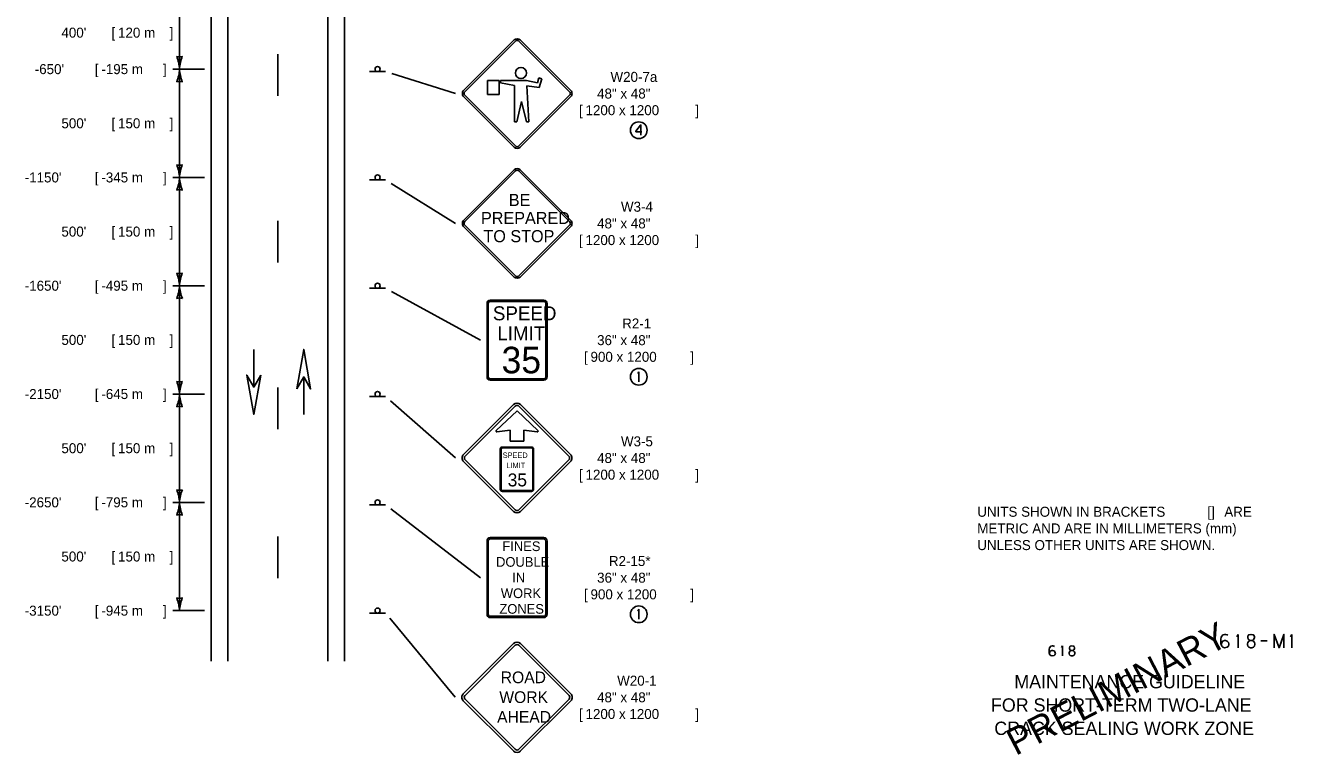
# Model space of a CAD drawing. Extents: x 49987.3 to 50021, y 49987.6 to 50011.4.
# Drawn here: x 49987.72 to 49995.31, y 50000.44 to 50004.82 of the extents above; entities that cross this region are included whole.
import ezdxf

# ---------------------------------------------------------------- set-up
doc = ezdxf.new("R2010")
doc.units = 0
for name, color, linetype in [('Level 1', 7, 'Continuous'), ('Level 2', 7, 'Continuous'), ('Level 3', 7, 'Continuous')]:
    doc.layers.add(name, color=color, linetype=linetype)

msp = doc.modelspace()

# ---------------------------------------------------------------- linework, layer by layer
at = {"layer": 'Level 1'}
for p, q in [((49988.8324, 50001.0011), (49988.8324, 50007.6183)), ((49988.9323, 50001.0011), (49988.9324, 50007.6183)), ((49989.5323, 50001.0011), (49989.5324, 50007.6183)), ((49989.6323, 50001.0011), (49989.6323, 50007.6183)), ((49990.6501, 50004.7296), (49990.346, 50004.4256)), ((49990.6571, 50004.7227), (49990.3531, 50004.4185)), ((49990.9822, 50004.4185), (49990.6784, 50004.7227)), ((49990.9894, 50004.4256), (49990.6854, 50004.7296)), ((49989.2324, 50004.3938), (49989.2324, 50004.6437)), ((49989.8783, 50004.5393), (49989.7824, 50004.5393)), ((49990.4894, 50004.402), (49990.4894, 50004.4869)), ((49990.4894, 50004.4869), (49990.5588, 50004.4869)), ((49990.5588, 50004.4869), (49990.5588, 50004.402)), ((49990.7232, 50004.4865), (49990.5667, 50004.4865)), ((49990.5667, 50004.4865), (49990.5667, 50004.4725)), ((49990.5667, 50004.4725), (49990.6516, 50004.4557)), ((49990.7887, 50004.4713), (49990.7232, 50004.4865)), ((49990.7984, 50004.5014), (49990.7887, 50004.4713)), ((49990.8149, 50004.4971), (49990.7984, 50004.5014)), ((49990.7998, 50004.4452), (49990.8149, 50004.4971)), ((49990.346, 50004.3904), (49990.6501, 50004.0864)), ((49990.3531, 50004.3974), (49990.6571, 50004.0934)), ((49990.5588, 50004.402), (49990.4894, 50004.402)), ((49990.6516, 50004.4557), (49990.6516, 50004.2391)), ((49990.6784, 50004.0934), (49990.9822, 50004.3974)), ((49990.6854, 50004.0864), (49990.9894, 50004.3904)), ((49990.7372, 50004.2391), (49990.7259, 50004.4536)), ((49990.7259, 50004.4536), (49990.7998, 50004.4452)), ((49990.6655, 50004.2391), (49990.6944, 50004.3612)), ((49990.6944, 50004.3612), (49990.7234, 50004.2391)), ((49990.6516, 50004.2391), (49990.6655, 50004.2391)), ((49990.7234, 50004.2391), (49990.7372, 50004.2391)), ((49990.6501, 50003.9502), (49990.346, 50003.6462)), ((49990.6571, 50003.9432), (49990.3531, 50003.6391)), ((49990.9822, 50003.6391), (49990.6784, 50003.9432)), ((49990.9894, 50003.6462), (49990.6854, 50003.9502)), ((49989.8783, 50003.8893), (49989.7824, 50003.8893)), ((49989.2324, 50003.3939), (49989.2324, 50003.6438)), ((49990.346, 50003.6109), (49990.6501, 50003.3069)), ((49990.3531, 50003.6179), (49990.6571, 50003.3139)), ((49990.6784, 50003.3139), (49990.9822, 50003.6179)), ((49990.6854, 50003.3069), (49990.9894, 50003.6109)), ((49989.8783, 50003.2393), (49989.7824, 50003.2393)), ((49990.4868, 50003.1479), (49990.4868, 50002.7079)), ((49990.4944, 50003.1479), (49990.4944, 50002.7079)), ((49990.828, 50003.1679), (49990.5055, 50003.1679)), ((49990.828, 50003.1599), (49990.5055, 50003.1599)), ((49990.8393, 50002.7079), (49990.8393, 50003.1479)), ((49990.8468, 50002.7079), (49990.8468, 50003.1479)), ((49989.0874, 50002.8722), (49989.0874, 50002.6463)), ((49989.0877, 50002.8722), (49989.0877, 50002.6463)), ((49989.2324, 50002.394), (49989.2324, 50002.6439)), ((49989.3871, 50002.4819), (49989.3871, 50002.708)), ((49989.3874, 50002.4819), (49989.3874, 50002.708)), ((49990.5055, 50002.696), (49990.828, 50002.696)), ((49990.5055, 50002.688), (49990.828, 50002.688)), ((49989.8783, 50002.5894), (49989.7824, 50002.5894)), ((49990.6454, 50002.5414), (49990.3461, 50002.2421)), ((49990.6555, 50002.5313), (49990.3562, 50002.232)), ((49990.6668, 50002.5029), (49990.5423, 50002.3856)), ((49990.6454, 50002.5414), (49990.6454, 50002.5414)), ((49990.6555, 50002.5313), (49990.6555, 50002.5313)), ((49990.7912, 50002.3856), (49990.6668, 50002.5029)), ((49990.9773, 50002.232), (49990.678, 50002.5313)), ((49990.9874, 50002.2421), (49990.6881, 50002.5414)), ((49990.5464, 50002.377), (49990.6264, 50002.387)), ((49990.6264, 50002.387), (49990.6264, 50002.3215)), ((49990.7071, 50002.3215), (49990.7071, 50002.387)), ((49990.7071, 50002.387), (49990.7871, 50002.377)), ((49990.5664, 50002.0326), (49990.5664, 50002.2739)), ((49990.5716, 50002.0326), (49990.5716, 50002.2739)), ((49990.5789, 50002.2864), (49990.7536, 50002.2864)), ((49990.5789, 50002.2812), (49990.7536, 50002.2812)), ((49990.6264, 50002.3215), (49990.7071, 50002.3215)), ((49990.6662, 50002.2864), (49990.6662, 50002.2864)), ((49990.7609, 50002.2739), (49990.7609, 50002.0326)), ((49990.7661, 50002.2739), (49990.7661, 50002.0326)), ((49990.3461, 50002.1993), (49990.6454, 50001.9)), ((49990.3562, 50002.2094), (49990.6555, 50001.9101)), ((49990.678, 50001.9101), (49990.9773, 50002.2094)), ((49990.6881, 50001.9), (49990.9874, 50002.1993)), ((49990.7536, 50002.0253), (49990.5789, 50002.0253)), ((49990.7536, 50002.0201), (49990.5789, 50002.0201)), ((49989.8783, 50001.9393), (49989.7824, 50001.9393)), ((49989.2324, 50001.4997), (49989.2324, 50001.7497)), ((49990.828, 50001.7426), (49990.5056, 50001.7426)), ((49990.828, 50001.7346), (49990.5056, 50001.7346)), ((49990.4868, 50001.7225), (49990.4868, 50001.2825)), ((49990.4944, 50001.7225), (49990.4944, 50001.2825)), ((49990.8393, 50001.2825), (49990.8393, 50001.7225)), ((49990.8468, 50001.2825), (49990.8468, 50001.7225)), ((49989.8783, 50001.2893), (49989.7824, 50001.2893)), ((49990.5056, 50001.2707), (49990.828, 50001.2707)), ((49990.5056, 50001.2626), (49990.828, 50001.2626)), ((49990.6455, 50001.1069), (49990.3446, 50000.8061)), ((49990.6555, 50001.0967), (49990.3548, 50000.796)), ((49990.6455, 50001.1069), (49990.6455, 50001.1069)), ((49990.6555, 50001.0967), (49990.6555, 50001.0967)), ((49990.9789, 50000.796), (49990.6782, 50001.0967)), ((49990.9891, 50000.8061), (49990.6884, 50001.1069)), ((49990.3446, 50000.7631), (49990.6455, 50000.4624)), ((49990.3548, 50000.7733), (49990.6555, 50000.4725)), ((49990.6669, 50000.7846), (49990.6669, 50000.7846)), ((49990.6669, 50000.7846), (49990.6669, 50000.7846)), ((49990.6669, 50000.7846), (49990.6669, 50000.7846)), ((49990.6782, 50000.4725), (49990.9789, 50000.7733)), ((49990.6884, 50000.4624), (49990.9891, 50000.7631))]:
    msp.add_line(p, q, dxfattribs=at)
for points in [[(49990.7982, 50004.5012), (49990.7984, 50004.5014)], [(49990.5585, 50004.402), (49990.5588, 50004.4024)], [(49990.7993, 50004.4453), (49990.8, 50004.4461)]]:
    msp.add_lwpolyline(points, dxfattribs=at)
for points in [[(49989.3454, 50002.6355), (49989.3871, 50002.8722), (49989.429, 50002.6355), (49989.3871, 50002.7077)], [(49989.1295, 50002.7186), (49989.0877, 50002.4821), (49989.0459, 50002.7186), (49989.0877, 50002.6463)]]:
    msp.add_lwpolyline(points, close=True, dxfattribs=at)
for centre, radius in [((49989.8303, 50004.5547), 0.0152), ((49990.6901, 50004.531), 0.0334), ((49989.8303, 50003.9045), 0.0152), ((49989.8303, 50003.2546), 0.0152), ((49989.8303, 50002.6046), 0.0152), ((49989.8303, 50001.9545), 0.0152), ((49989.8303, 50001.3046), 0.0152)]:
    msp.add_circle(centre, radius, dxfattribs=at)
for centre, radius, start, end in [((49990.6677, 50004.7121), 0.025, 45, 135), ((49990.6677, 50004.7121), 0.015, 45, 135), ((49990.3637, 50004.4081), 0.025, 135, 225), ((49990.3637, 50004.4081), 0.015, 135, 225), ((49990.9717, 50004.4081), 0.015, 315, 45.00024), ((49990.9717, 50004.4081), 0.025, 315, 45.00024), ((49990.6677, 50004.104), 0.025, 225, 314.99957), ((49990.6677, 50004.104), 0.015, 225, 314.99957), ((49990.6677, 50003.9326), 0.025, 45, 135), ((49990.6677, 50003.9326), 0.015, 45, 135), ((49990.3637, 50003.6286), 0.025, 135, 225), ((49990.3637, 50003.6286), 0.015, 135, 225), ((49990.9717, 50003.6286), 0.015, 315, 45.00024), ((49990.9717, 50003.6286), 0.025, 315, 45.00024), ((49990.6677, 50003.3246), 0.025, 225, 314.99957), ((49990.6677, 50003.3246), 0.015, 225, 314.99957), ((49990.6668, 50002.52), 0.0302, 45.00007, 134.99993), ((49990.6668, 50002.52), 0.016, 45.00007, 134.99993), ((49990.5459, 50002.382), 0.00508, 134.62874, 275.82948), ((49990.7876, 50002.382), 0.00509, 264.38259, 45.16491), ((49990.5789, 50002.2739), 0.0125, 90, 180), ((49990.5789, 50002.2739), 0.00728, 90, 180), ((49990.7536, 50002.2739), 0.0125, 360, 90), ((49990.7536, 50002.2739), 0.00728, 360, 90), ((49990.3674, 50002.2207), 0.0302, 134.99993, 225.00008), ((49990.3674, 50002.2207), 0.016, 134.99993, 225.00008), ((49990.9661, 50002.2207), 0.016, 314.99993, 45.00007), ((49990.9661, 50002.2207), 0.0302, 314.99993, 45.00008), ((49990.5789, 50002.0326), 0.0125, 180, 270), ((49990.5789, 50002.0326), 0.00728, 180, 270), ((49990.7536, 50002.0326), 0.00728, 270, 360), ((49990.7536, 50002.0326), 0.0125, 270, 360), ((49990.6668, 50001.9214), 0.0302, 225.00007, 314.99993), ((49990.6668, 50001.9214), 0.016, 225.00007, 314.99993), ((49990.6668, 50001.0852), 0.0304, 45.00008, 134.99993), ((49990.6668, 50001.0852), 0.016, 45.00008, 134.99993), ((49990.366, 50000.7845), 0.0304, 134.99993, 225.00008), ((49990.366, 50000.7845), 0.016, 134.99993, 225.00008), ((49990.9675, 50000.7845), 0.016, 314.99993, 45.00007), ((49990.9675, 50000.7845), 0.0304, 314.99993, 45.00008), ((49990.6668, 50000.4837), 0.0304, 225.00007, 314.99993), ((49990.6668, 50000.4837), 0.016, 225.00007, 314.99993)]:
    msp.add_arc(centre, radius, start, end, dxfattribs=at)
for centre, major_axis, start_param, end_param in [((49990.5057, 50003.148), (0, 0.02), 0, 1.570796), ((49990.5057, 50003.148), (0, 0.012), 0, 1.570796), ((49990.8282, 50003.148), (0, 0.02), 4.712389, 6.283185), ((49990.8282, 50003.148), (0, 0.012), 4.712389, 6.283185), ((49990.5057, 50002.7081), (0, -0.02), 4.712389, 6.283185), ((49990.5057, 50002.7081), (0, -0.012), 4.712389, 6.283185), ((49990.8282, 50002.7081), (0, -0.02), 0, 1.570796), ((49990.8282, 50002.7081), (0, -0.012), 0, 1.570796), ((49990.5055, 50001.7227), (0, 0.02), 0, 1.570796), ((49990.5055, 50001.7227), (0, 0.012), 0, 1.570796), ((49990.828, 50001.7227), (0, 0.02), 4.712389, 6.283185), ((49990.828, 50001.7227), (0, 0.012), 4.712389, 6.283185), ((49990.5055, 50001.2827), (0, -0.02), 4.712389, 6.283185), ((49990.5055, 50001.2827), (0, -0.012), 4.712389, 6.283185), ((49990.828, 50001.2827), (0, -0.02), 0, 1.570796), ((49990.828, 50001.2827), (0, -0.012), 0, 1.570796)]:
    msp.add_ellipse(centre, major_axis=major_axis, ratio=0.9375, start_param=start_param, end_param=end_param, dxfattribs=at)
at = {"layer": 'Level 2'}
for p, q in [((49991.397, 50002.738), (49991.3911, 50002.7276)), ((49991.397, 50002.738), (49991.397, 50002.678)), ((49991.397, 50001.3125), (49991.3911, 50001.3021)), ((49991.397, 50001.3125), (49991.397, 50001.2525)), ((49994.9929, 50001.1623), (49994.985, 50001.1484)), ((49994.9929, 50001.1623), (49994.9929, 50001.0823)), ((49995.1271, 50001.1226), (49995.1661, 50001.1226)), ((49995.3129, 50001.1623), (49995.305, 50001.1484)), ((49995.3129, 50001.1623), (49995.3129, 50001.0823)), ((49993.9376, 50001.0929), (49993.9317, 50001.0825)), ((49993.9376, 50001.0929), (49993.9376, 50001.0329))]:
    msp.add_line(p, q, dxfattribs=at)
for points in [[(49991.4144, 50004.1791), (49991.3803, 50004.1791), (49991.3803, 50004.1815), (49991.4068, 50004.2183), (49991.4101, 50004.2183), (49991.4101, 50004.1583)], [(49994.9299, 50001.1566), (49994.9255, 50001.1591), (49994.918, 50001.1623), (49994.9104, 50001.1623), (49994.9003, 50001.1591), (49994.8896, 50001.1459), (49994.8871, 50001.1333), (49994.8871, 50001.1195), (49994.8884, 50001.1075), (49994.8934, 50001.0918), (49994.9003, 50001.0848), (49994.9104, 50001.0823), (49994.9268, 50001.0855), (49994.9331, 50001.0918), (49994.9369, 50001.1012), (49994.9362, 50001.1062), (49994.9331, 50001.1138), (49994.9261, 50001.122), (49994.9167, 50001.1245), (49994.9098, 50001.1251), (49994.8997, 50001.122), (49994.8934, 50001.1144), (49994.8903, 50001.1018)], [(49995.0736, 50001.1264), (49995.083, 50001.1295), (49995.0868, 50001.1333), (49995.0893, 50001.1428), (49995.0893, 50001.1465), (49995.0861, 50001.1566), (49995.0824, 50001.1591), (49995.0698, 50001.1623), (49995.0565, 50001.1591), (49995.0528, 50001.1566), (49995.0496, 50001.1465), (49995.0496, 50001.1428), (49995.0521, 50001.1333), (49995.0559, 50001.1295), (49995.0654, 50001.1264), (49995.0736, 50001.1264), (49995.083, 50001.122), (49995.0893, 50001.1144), (49995.0924, 50001.1056), (49995.0924, 50001.1025), (49995.0899, 50001.0918), (49995.083, 50001.0848), (49995.0742, 50001.0823), (49995.0654, 50001.0823), (49995.0565, 50001.0848), (49995.0496, 50001.0918), (49995.0471, 50001.1018), (49995.0471, 50001.1056), (49995.0503, 50001.1144), (49995.0565, 50001.122), (49995.0654, 50001.1264)], [(49995.2071, 50001.0823), (49995.2071, 50001.1623), (49995.2373, 50001.0823), (49995.2663, 50001.1623), (49995.2663, 50001.0823)], [(49993.8903, 50001.0886), (49993.887, 50001.0905), (49993.8813, 50001.0929), (49993.8757, 50001.0929), (49993.8681, 50001.0905), (49993.8601, 50001.0806), (49993.8582, 50001.0712), (49993.8582, 50001.0608), (49993.8591, 50001.0518), (49993.8629, 50001.04), (49993.8681, 50001.0348), (49993.8757, 50001.0329), (49993.888, 50001.0353), (49993.8927, 50001.04), (49993.8955, 50001.0471), (49993.895, 50001.0509), (49993.8927, 50001.0565), (49993.8875, 50001.0627), (49993.8804, 50001.0646), (49993.8752, 50001.065), (49993.8676, 50001.0627), (49993.8629, 50001.057), (49993.8606, 50001.0475)], [(49993.998, 50001.066), (49994.0051, 50001.0683), (49994.008, 50001.0712), (49994.0099, 50001.0783), (49994.0099, 50001.0811), (49994.0075, 50001.0886), (49994.0047, 50001.0905), (49993.9952, 50001.0929), (49993.9853, 50001.0905), (49993.9825, 50001.0886), (49993.9801, 50001.0811), (49993.9801, 50001.0783), (49993.982, 50001.0712), (49993.9848, 50001.0683), (49993.9919, 50001.066), (49993.998, 50001.066), (49994.0051, 50001.0627), (49994.0099, 50001.057), (49994.0122, 50001.0504), (49994.0122, 50001.048), (49994.0103, 50001.04), (49994.0051, 50001.0348), (49993.9985, 50001.0329), (49993.9919, 50001.0329), (49993.9853, 50001.0348), (49993.9801, 50001.04), (49993.9782, 50001.0475), (49993.9782, 50001.0504), (49993.9806, 50001.057), (49993.9853, 50001.0627), (49993.9919, 50001.066)]]:
    msp.add_lwpolyline(points, dxfattribs=at)
for centre in [(49991.3971, 50004.1881), (49991.397, 50002.708), (49991.397, 50001.2825)]:
    msp.add_circle(centre, 0.05, dxfattribs=at)
at = {"layer": 'Level 3'}
for p, q in [((49988.6425, 50001.3045), (49988.6425, 50005.2045)), ((49988.6024, 50004.5545), (49988.7925, 50004.5545)), ((49989.9164, 50004.5274), (49990.2987, 50004.4081)), ((49988.6024, 50003.9045), (49988.7924, 50003.9045)), ((49989.9123, 50003.8682), (49990.2987, 50003.6286)), ((49988.6025, 50003.2545), (49988.7924, 50003.2545)), ((49989.9133, 50003.2201), (49990.4468, 50002.9279)), ((49988.6024, 50002.6045), (49988.7924, 50002.6045)), ((49989.9083, 50002.563), (49990.2972, 50002.2207)), ((49988.6024, 50001.9545), (49988.7924, 50001.9545)), ((49989.91, 50001.915), (49990.4468, 50001.5025)), ((49988.6025, 50001.3045), (49988.7924, 50001.3045)), ((49989.9037, 50001.2585), (49990.2956, 50000.7845))]:
    msp.add_line(p, q, dxfattribs=at)
for centre, radius, start, end in [((49988.6425, 50004.6827), 0.0548, 252.13882, 287.86118), ((49988.4098, 50004.543), 0.233, 2.82731, 22.07716), ((49988.8646, 50004.5454), 0.2223, 157.45601, 177.63952), ((49988.4204, 50004.5637), 0.2223, 337.45601, 357.63952), ((49988.8752, 50004.566), 0.233, 182.82731, 202.07716), ((49988.6425, 50004.4263), 0.0548, 72.13882, 107.86118), ((49988.6425, 50004.0327), 0.0548, 252.13882, 287.86118), ((49988.4098, 50003.893), 0.233, 2.82731, 22.07716), ((49988.8646, 50003.8954), 0.2223, 157.45601, 177.63952), ((49988.4204, 50003.9137), 0.2223, 337.45601, 357.63952), ((49988.8752, 50003.916), 0.233, 182.82731, 202.07716), ((49988.6425, 50003.7763), 0.0548, 72.13882, 107.86118), ((49988.6425, 50003.3827), 0.0548, 252.14219, 287.86455), ((49988.4098, 50003.243), 0.233, 2.83068, 22.08053), ((49988.8646, 50003.2454), 0.2223, 157.45938, 177.64289), ((49988.4203, 50003.2636), 0.2223, 337.47849, 357.662), ((49988.8752, 50003.2661), 0.233, 182.84979, 202.09964), ((49988.6425, 50003.1263), 0.0548, 72.1613, 107.88366), ((49988.6424, 50002.7327), 0.0548, 252.1613, 287.88366), ((49988.4098, 50002.5929), 0.233, 2.84979, 22.09964), ((49988.8646, 50002.5954), 0.2223, 157.47849, 177.662), ((49988.4204, 50002.6138), 0.2223, 337.43016, 357.61366), ((49988.8752, 50002.6159), 0.233, 182.80146, 202.05131), ((49988.6424, 50002.4763), 0.0548, 72.11296, 107.83532), ((49988.6425, 50002.0827), 0.0548, 252.11296, 287.83532), ((49988.4098, 50001.9431), 0.233, 2.80146, 22.05131), ((49988.8646, 50001.9453), 0.2223, 157.43016, 177.61366), ((49988.4203, 50001.9637), 0.2223, 337.45938, 357.64289), ((49988.6425, 50001.8263), 0.0548, 72.14219, 107.86455), ((49988.8752, 50001.966), 0.233, 182.83068, 202.08053), ((49988.6425, 50001.4327), 0.0548, 252.14219, 287.86455), ((49988.4098, 50001.293), 0.233, 2.83068, 22.08053), ((49988.8646, 50001.2954), 0.2223, 157.45938, 177.64289)]:
    msp.add_arc(centre, radius, start, end, dxfattribs=at)

# ---------------------------------------------------------------- texts
at = {"layer": 'Level 1'}
for s, height, p in [('BE', 0.07249, (49990.6175, 50003.7333)), ('PREPARED', 0.07249, (49990.4506, 50003.6247)), ('TO STOP', 0.07249, (49990.4653, 50003.5158)), ('SPEED', 0.08409, (49990.522, 50003.0469)), ('LIMIT', 0.08409, (49990.5486, 50002.9268)), ('35', 0.15912, (49990.5741, 50002.729)), ('ROAD', 0.07021, (49990.569, 50000.8692)), ('WORK', 0.07021, (49990.5604, 50000.7504)), ('AHEAD', 0.07021, (49990.5473, 50000.6317))]:
    msp.add_text(s, height=height, dxfattribs=at).set_placement(p)
for s, height, p in [('SPEED', 0.03301, (49990.5809, 50002.2207)), ('LIMIT', 0.03301, (49990.6028, 50002.1597)), ('35', 0.07775, (49990.6108, 50002.0503)), ('FINES', 0.05799, (49990.5788, 50001.6621)), ('DOUBLE', 0.05799, (49990.5412, 50001.568)), ('IN', 0.05799, (49990.6378, 50001.474)), ('WORK', 0.05799, (49990.5697, 50001.3799)), ('ZONES', 0.05799, (49990.561, 50001.2861))]:
    msp.add_text(s, height=height, rotation=360, dxfattribs=at).set_placement(p)
at = {"layer": 'Level 2'}
for s, height, p in [("400' ", 0.05999, (49987.9341, 50004.7435)), ('[', 0.06, (49988.234, 50004.7435)), ('120 m', 0.05999, (49988.2737, 50004.7435)), (']', 0.06, (49988.5826, 50004.7435)), ("-650' ", 0.05999, (49987.7741, 50004.5245)), ('[', 0.06, (49988.134, 50004.5245)), ('-195 m', 0.05999, (49988.1737, 50004.5245)), (']', 0.06, (49988.5426, 50004.5245)), ('W20-7a', 0.05999, (49991.2273, 50004.478)), ('48" x 48"', 0.05999, (49991.147, 50004.3781)), ('[', 0.06, (49991.0379, 50004.2781)), ('1200 x 1200', 0.059993, (49991.0775, 50004.2781)), (']', 0.06, (49991.7365, 50004.2781)), ("500' ", 0.05999, (49987.9341, 50004.1995)), ('[', 0.06, (49988.234, 50004.1995)), ('150 m', 0.05999, (49988.2737, 50004.1995)), (']', 0.06, (49988.5826, 50004.1995)), ("-1150' ", 0.05999, (49987.714, 50003.8745)), ('[', 0.06, (49988.134, 50003.8745)), ('-345 m', 0.05999, (49988.1737, 50003.8745)), (']', 0.06, (49988.5426, 50003.8745)), ('W3-4', 0.05999, (49991.2901, 50003.6986)), ('48" x 48"', 0.05999, (49991.147, 50003.5986)), ("500' ", 0.05999, (49987.934, 50003.5495)), ('[', 0.06, (49988.234, 50003.5495)), ('150 m', 0.05999, (49988.2737, 50003.5495)), (']', 0.06, (49988.5826, 50003.5495)), ('[', 0.06, (49991.0379, 50003.4986)), ('1200 x 1200', 0.059993, (49991.0775, 50003.4986)), (']', 0.06, (49991.7365, 50003.4986)), ("-1650' ", 0.05999, (49987.7141, 50003.2245)), ('[', 0.06, (49988.134, 50003.2245)), ('-495 m', 0.05999, (49988.1737, 50003.2245)), (']', 0.06, (49988.5426, 50003.2245)), ('R2-1', 0.05999, (49991.2974, 50002.9979)), ("500' ", 0.05999, (49987.9341, 50002.8995)), ('[', 0.06, (49988.234, 50002.8995)), ('150 m', 0.05999, (49988.2737, 50002.8995)), (']', 0.06, (49988.5826, 50002.8995)), ('36" x 48"', 0.05999, (49991.147, 50002.8979)), ('[', 0.06, (49991.0679, 50002.798)), ('900 x 1200', 0.05999, (49991.1075, 50002.798)), (']', 0.06, (49991.7065, 50002.798)), ("-2150' ", 0.05999, (49987.7141, 50002.5745)), ('[', 0.06, (49988.134, 50002.5745)), ('-645 m', 0.05999, (49988.1737, 50002.5745)), (']', 0.06, (49988.5426, 50002.5745)), ('W3-5', 0.05999, (49991.2901, 50002.2907)), ("500' ", 0.05999, (49987.9341, 50002.2495)), ('[', 0.06, (49988.234, 50002.2495)), ('150 m', 0.05999, (49988.2737, 50002.2495)), (']', 0.06, (49988.5826, 50002.2495)), ('48" x 48"', 0.05999, (49991.147, 50002.1907)), ('[', 0.06, (49991.0379, 50002.0907)), ('1200 x 1200', 0.059993, (49991.0775, 50002.0907)), (']', 0.06, (49991.7365, 50002.0907)), ("-2650' ", 0.05999, (49987.714, 50001.9245)), ('[', 0.06, (49988.134, 50001.9245)), ('-795 m', 0.05999, (49988.1737, 50001.9245)), (']', 0.06, (49988.5426, 50001.9245)), ('UNITS SHOWN IN BRACKETS ', 0.06, (49993.4272, 50001.868)), ('[]', 0.06, (49994.8072, 50001.868)), (' ARE ', 0.06, (49994.8866, 50001.868)), ('METRIC AND ARE IN MILLIMETERS (mm) ', 0.06, (49993.4272, 50001.768)), ('UNLESS OTHER UNITS ARE SHOWN.', 0.06, (49993.4272, 50001.668)), ("500' ", 0.05999, (49987.934, 50001.5995)), ('[', 0.06, (49988.234, 50001.5995)), ('150 m', 0.05999, (49988.2737, 50001.5995)), (']', 0.06, (49988.5826, 50001.5995)), ('R2-15*', 0.05999, (49991.2178, 50001.5725)), ('36" x 48"', 0.05999, (49991.147, 50001.4725)), ('[', 0.06, (49991.0679, 50001.3725)), ('900 x 1200', 0.05999, (49991.1075, 50001.3725)), (']', 0.06, (49991.7065, 50001.3725)), ("-3150' ", 0.05999, (49987.7141, 50001.2745)), ('[', 0.06, (49988.134, 50001.2745)), ('-945 m', 0.05999, (49988.1737, 50001.2745)), (']', 0.06, (49988.5426, 50001.2745)), ('W20-1', 0.05999, (49991.2674, 50000.8545)), ('MAINTENANCE GUIDELINE', 0.08, (49993.6493, 50000.8383)), ('48" x 48"', 0.05999, (49991.147, 50000.7545)), ('FOR SHORT-TERM TWO-LANE', 0.08, (49993.5093, 50000.6983)), ('[', 0.06, (49991.0379, 50000.6545)), ('1200 x 1200', 0.059993, (49991.0775, 50000.6545)), (']', 0.06, (49991.7365, 50000.6545)), ('CRACK SEALING WORK ZONE', 0.08, (49993.5293, 50000.5584))]:
    msp.add_text(s, height=height, dxfattribs=at).set_placement(p)
msp.add_text('PRELIMINARY', height=0.16, rotation=27.5, dxfattribs=at).set_placement((49993.6575, 50000.432))

doc.saveas('drawing.dxf')
